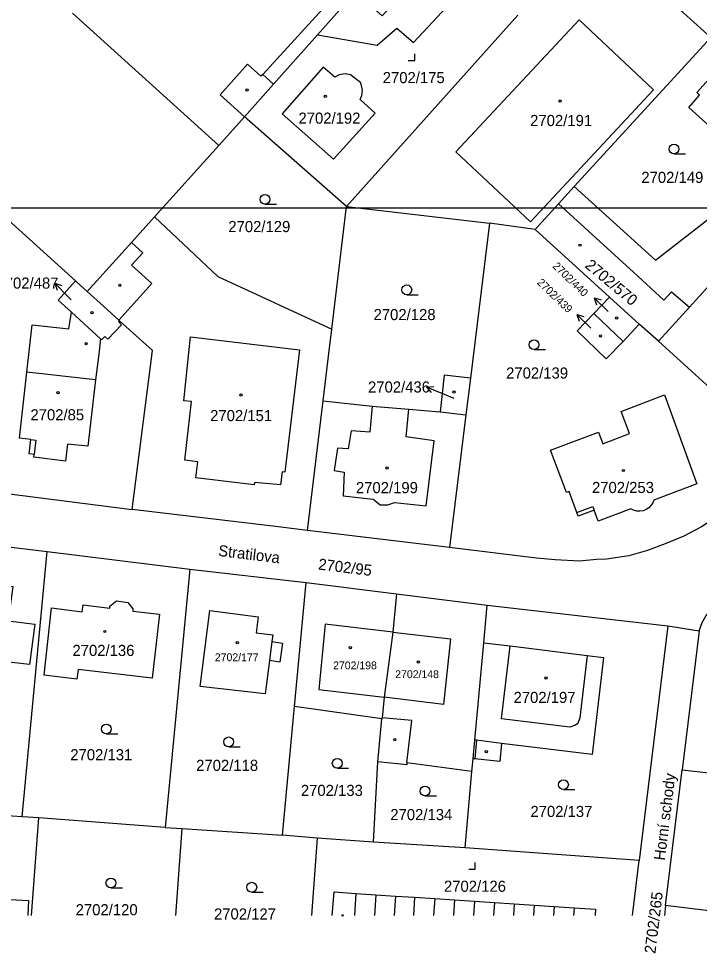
# Model space of a CAD drawing. Extents: x -496682 to -495907, y -1088575 to -1088018.
# Drawn here: x -496399.3 to -496295.2, y -1088575.2 to -1088432.3 of the extents above; entities that cross this region are included whole.
import ezdxf

# ---------------------------------------------------------------- set-up
doc = ezdxf.new("R2010")
doc.units = 0
for name, color, linetype in [('Hranice parcel', 7, 'Continuous'), ('Parcelní čísla', 7, 'Continuous'), ('Pop  PČ popisy', 7, 'Continuous'), ('Vnitřní kresba', 7, 'Continuous'), ('Vrstva 63', 7, 'Continuous'), ('Značky budov', 7, 'Continuous'), ('Značky kultur', 7, 'Continuous')]:
    doc.layers.add(name, color=color, linetype=linetype)

msp = doc.modelspace()

# ---------------------------------------------------------------- linework, layer by layer
at = {"layer": 'Hranice parcel'}
for p, q in [((-496322.98, -1088431.74), (-496349.17, -1088461.01)), ((-496368.72, -1088451.67), (-496364.78, -1088447.29)), ((-496349.17, -1088461.01), (-496364.78, -1088447.29)), ((-496378.57, -1088462.59), (-496368.72, -1088451.67)), ((-496316.74, -1088460.58), (-496314.33, -1088457.95)), ((-496320.32, -1088464.49), (-496316.74, -1088460.58)), ((-496351.43, -1088479.75), (-496349.17, -1088461.01)), ((-496349.17, -1088461.01), (-496327.31, -1088463.52)), ((-496390.64, -1088472.36), (-496401.99, -1088462.09)), ((-496327.31, -1088463.52), (-496330.22, -1088487.27)), ((-496320.32, -1088464.49), (-496327.31, -1088463.52)), ((-496308.94, -1088474.84), (-496320.32, -1088464.49)), ((-496311.35, -1088477.35), (-496308.94, -1088474.84)), ((-496304.39, -1088478.97), (-496308.94, -1088474.84)), ((-496386.81, -1088481.22), (-496391.24, -1088477.18)), ((-496306.88, -1088481.63), (-496311.35, -1088477.35)), ((-496296.73, -1088476.39), (-496301.48, -1088481.61)), ((-496304.39, -1088478.97), (-496306.88, -1088481.63)), ((-496301.48, -1088481.61), (-496304.39, -1088478.97)), ((-496301.48, -1088481.61), (-496282.64, -1088498.73)), ((-496330.22, -1088487.27), (-496330.91, -1088492.86)), ((-496355.16, -1088510.55), (-496352.76, -1088490.73)), ((-496334.86, -1088492.38), (-496330.91, -1088492.86)), ((-496330.91, -1088492.86), (-496333.4, -1088513.15)), ((-496333.4, -1088513.15), (-496355.16, -1088510.55)), ((-496413.5, -1088511.53), (-496394.97, -1088513.78)), ((-496398.8, -1088554.34), (-496394.97, -1088513.78)), ((-496394.97, -1088513.78), (-496373.13, -1088516.44)), ((-496373.13, -1088516.44), (-496376.91, -1088555.96)), ((-496373.13, -1088516.44), (-496355.34, -1088518.51)), ((-496357.11, -1088537.48), (-496355.34, -1088518.51)), ((-496355.34, -1088518.51), (-496341.52, -1088520.23)), ((-496341.52, -1088520.23), (-496327.65, -1088521.96)), ((-496328.17, -1088527.72), (-496327.65, -1088521.96)), ((-496327.65, -1088521.96), (-496300.01, -1088525.15)), ((-496300.01, -1088525.15), (-496304.43, -1088561.01)), ((-496300.01, -1088525.15), (-496295.23, -1088525.87)), ((-496295.23, -1088525.87), (-496297.81, -1088547.13)), ((-496358.95, -1088557.14), (-496357.11, -1088537.48)), ((-496343.76, -1088539.36), (-496357.11, -1088537.48)), ((-496344.37, -1088545.92), (-496343.76, -1088539.36)), ((-496345.03, -1088558.23), (-496344.37, -1088545.92)), ((-496330.02, -1088547.42), (-496329.78, -1088545.45)), ((-496331.02, -1088559.09), (-496330.02, -1088547.42)), ((-496300.36, -1088567.89), (-496297.81, -1088547.13)), ((-496297.81, -1088547.13), (-496255.13, -1088552.31)), ((-496398.8, -1088554.34), (-496417.53, -1088552.98)), ((-496396.26, -1088554.52), (-496398.8, -1088554.34)), ((-496397.38, -1088569.45), (-496396.26, -1088554.52)), ((-496376.91, -1088555.96), (-496396.26, -1088554.52)), ((-496376.91, -1088555.96), (-496374.34, -1088556.11)), ((-496375.31, -1088569.45), (-496374.34, -1088556.11)), ((-496374.34, -1088556.11), (-496358.95, -1088557.14)), ((-496353.66, -1088557.62), (-496358.95, -1088557.14)), ((-496353.66, -1088557.62), (-496354.53, -1088569.45)), ((-496345.03, -1088558.23), (-496353.66, -1088557.62)), ((-496331.02, -1088559.09), (-496345.03, -1088558.23)), ((-496304.43, -1088561.01), (-496331.02, -1088559.09)), ((-496305.44, -1088569.45), (-496304.43, -1088561.01)), ((-496347.76, -1088566.06), (-496347.98, -1088569.45)), ((-496347.76, -1088566.06), (-496344.71, -1088566.26)), ((-496344.71, -1088566.26), (-496344.92, -1088569.45)), ((-496344.71, -1088566.26), (-496341.67, -1088566.46)), ((-496341.67, -1088566.46), (-496341.87, -1088569.45)), ((-496341.67, -1088566.46), (-496338.77, -1088566.65)), ((-496338.77, -1088566.65), (-496338.95, -1088569.45)), ((-496338.77, -1088566.65), (-496335.68, -1088566.85)), ((-496335.68, -1088566.85), (-496335.85, -1088569.45)), ((-496335.68, -1088566.85), (-496332.64, -1088567.05)), ((-496332.64, -1088567.05), (-496332.8, -1088569.45)), ((-496332.64, -1088567.05), (-496329.59, -1088567.25)), ((-496329.59, -1088567.25), (-496329.73, -1088569.45)), ((-496329.59, -1088567.25), (-496326.55, -1088567.45)), ((-496326.55, -1088567.45), (-496326.68, -1088569.45)), ((-496326.55, -1088567.45), (-496323.51, -1088567.65)), ((-496323.51, -1088567.65), (-496323.63, -1088569.45)), ((-496323.51, -1088567.65), (-496320.46, -1088567.85)), ((-496320.46, -1088567.85), (-496320.57, -1088569.45)), ((-496320.46, -1088567.85), (-496317.42, -1088568.05)), ((-496317.42, -1088568.05), (-496317.51, -1088569.45)), ((-496317.42, -1088568.05), (-496314.37, -1088568.25)), ((-496314.37, -1088568.25), (-496314.45, -1088569.45)), ((-496300.36, -1088567.89), (-496300.54, -1088569.45))]:
    msp.add_line(p, q, dxfattribs=at)
for points in [[(-496353.62, -1088434.72), (-496347.79, -1088428.16), (-496343.74, -1088431.85), (-496329.03, -1088415.71), (-496329.94, -1088414.89), (-496330.57, -1088414.27), (-496328.66, -1088412.18), (-496329.87, -1088411.04), (-496330.29, -1088409.02), (-496320.05, -1088397.68)], [(-496353.62, -1088434.72), (-496344.49, -1088436.33), (-496341.48, -1088433.73), (-496338.95, -1088435.92), (-496329.51, -1088425.77)], [(-496286.81, -1088427.89), (-496293.46, -1088435.15), (-496314.33, -1088457.95)], [(-496391.09, -1088431.4), (-496372.42, -1088448.31), (-496368.72, -1088451.67)], [(-496364.78, -1088447.29), (-496360.33, -1088442.29), (-496353.62, -1088434.72)], [(-496283.32, -1088454.6), (-496289.39, -1088449.15), (-496290.42, -1088450.31), (-496292.57, -1088448.38), (-496293.21, -1088449.09), (-496296.84, -1088445.84), (-496295.16, -1088443.98), (-496295.61, -1088443.57), (-496287.2, -1088434.24), (-496282.48, -1088438.48), (-496281.67, -1088437.59), (-496278.91, -1088440.14), (-496279.72, -1088440.96), (-496274.93, -1088445.27)], [(-496350.98, -1088441.21), (-496352.73, -1088439.67), (-496359.04, -1088446.84), (-496351.17, -1088453.77), (-496344.79, -1088446.72), (-496347.09, -1088444.64), (-496346.85, -1088444.04), (-496346.74, -1088443.18), (-496346.99, -1088442.1), (-496348.56, -1088440.87), (-496349.36, -1088440.72), (-496350.32, -1088440.88), (-496350.98, -1088441.21)], [(-496268.01, -1088444.81), (-496274.79, -1088452.23), (-496288.2, -1088467.01), (-496292.3, -1088471.51), (-496296.73, -1088476.39)], [(-496314.33, -1088457.95), (-496301.91, -1088469.21), (-496284.09, -1088455.32), (-496283.32, -1088454.6)], [(-496316.74, -1088460.58), (-496305.3, -1088471.05), (-496300.65, -1088475.31), (-496299.49, -1088474.04), (-496296.73, -1088476.39)], [(-496388.84, -1088473.99), (-496382.08, -1088466.49), (-496378.57, -1088462.59)], [(-496378.57, -1088462.59), (-496368.85, -1088471.68), (-496351.43, -1088479.75)], [(-496391.24, -1088477.18), (-496393.28, -1088475.32), (-496390.64, -1088472.36)], [(-496390.64, -1088472.36), (-496390.47, -1088472.51), (-496388.84, -1088473.99)], [(-496388.84, -1088473.99), (-496386.37, -1088476.23), (-496383.99, -1088478.38), (-496383.91, -1088478.46)], [(-496386.81, -1088481.22), (-496387.08, -1088483.58), (-496387.6, -1088487.48), (-496388.73, -1088497.67), (-496391.86, -1088497.32), (-496392.17, -1088499.92), (-496397, -1088499.33), (-496396.95, -1088498.93), (-496397.74, -1088498.83), (-496397.47, -1088496.62), (-496399.19, -1088496.41), (-496398.08, -1088486.32), (-496397.28, -1088479.07), (-496391.65, -1088479.71), (-496391.24, -1088477.18)], [(-496306.88, -1088481.63), (-496309.46, -1088484.31), (-496313.92, -1088480.03), (-496311.35, -1088477.35)], [(-496383.91, -1088478.46), (-496384.05, -1088478.58), (-496383.6, -1088479.07), (-496385.69, -1088481.28), (-496386.15, -1088480.86), (-496386.65, -1088481.37), (-496386.81, -1088481.22)], [(-496381.96, -1088507.33), (-496378.87, -1088483.01), (-496383.91, -1088478.46)], [(-496352.76, -1088490.73), (-496351.88, -1088483.47), (-496351.43, -1088479.75)], [(-496330.22, -1088487.27), (-496334.22, -1088486.77), (-496334.86, -1088492.38)], [(-496305.69, -1088507.24), (-496310.68, -1088509.11), (-496311.29, -1088507.46), (-496313.75, -1088508.38), (-496313.97, -1088507.79), (-496315.1, -1088504.6), (-496315.52, -1088504.76), (-496317.97, -1088498.28), (-496310.64, -1088495.51), (-496309.98, -1088497.27), (-496305.9, -1088495.73), (-496307.18, -1088492.33), (-496300.54, -1088489.82), (-496295.6, -1088503.41), (-496302.16, -1088505.89)], [(-496352.76, -1088490.73), (-496345.27, -1088491.55), (-496339.65, -1088492), (-496334.86, -1088492.38)], [(-496282.64, -1088498.73), (-496287, -1088503.42), (-496289.92, -1088506.42), (-496292.31, -1088508.31), (-496294.86, -1088509.98), (-496297.59, -1088511.42), (-496300.41, -1088512.61), (-496303.13, -1088513.62), (-496305.98, -1088514.4), (-496309.41, -1088514.94), (-496310.93, -1088514.97), (-496313.55, -1088515.26), (-496317.24, -1088515.06), (-496320.12, -1088514.76), (-496333.4, -1088513.15)], [(-496427.43, -1088500.69), (-496425.57, -1088501.8), (-496381.96, -1088507.33)], [(-496302.16, -1088505.89), (-496302.34, -1088506.34), (-496302.61, -1088506.75), (-496302.95, -1088507.09), (-496303.36, -1088507.35), (-496303.82, -1088507.53), (-496304.3, -1088507.6), (-496304.79, -1088507.58), (-496305.26, -1088507.46), (-496305.69, -1088507.24)], [(-496355.16, -1088510.55), (-496360.04, -1088509.96), (-496381.96, -1088507.33)], [(-496295.23, -1088525.87), (-496294.76, -1088524.6), (-496294.18, -1088523.56), (-496292.73, -1088521.72), (-496280.44, -1088508.2)], [(-496401.7, -1088530.59), (-496411.17, -1088529.49), (-496410.56, -1088524.24), (-496411.46, -1088524.14), (-496410.89, -1088519.24), (-496410.59, -1088519.28), (-496410.48, -1088518.4), (-496408.38, -1088518.63), (-496408.48, -1088519.52), (-496405.68, -1088519.85), (-496405.48, -1088518.47), (-496400.24, -1088519.14), (-496400.91, -1088524.37), (-496396.87, -1088524.88), (-496397.69, -1088531.06), (-496401.7, -1088530.59)], [(-496341.52, -1088520.23), (-496342.09, -1088526.09), (-496343.43, -1088536.06), (-496343.75, -1088539.19), (-496343.76, -1088539.36)], [(-496385.39, -1088522.41), (-496385.39, -1088522.11), (-496384.36, -1088521.3), (-496382.62, -1088521.57), (-496381.87, -1088522.55), (-496381.89, -1088522.88), (-496377.78, -1088523.37), (-496378.93, -1088533.14), (-496390.24, -1088531.8), (-496390.41, -1088533.27), (-496395.43, -1088532.68), (-496394.32, -1088522.39), (-496389.59, -1088522.97), (-496389.46, -1088521.92), (-496385.39, -1088522.41)], [(-496360.97, -1088530.45), (-496361.62, -1088535.52), (-496371.55, -1088534.42), (-496370.09, -1088522.81), (-496362.68, -1088523.75), (-496362.99, -1088526.22), (-496360.46, -1088526.49), (-496360.59, -1088527.55), (-496358.97, -1088527.77), (-496359.36, -1088530.67), (-496360.97, -1088530.45)], [(-496329.78, -1088545.45), (-496329.53, -1088542.61), (-496328.17, -1088527.72)], [(-496328.17, -1088527.72), (-496324.13, -1088528.21), (-496312.38, -1088529.66)], [(-496312.38, -1088529.66), (-496309.87, -1088529.96), (-496311.62, -1088544.81), (-496325.46, -1088543.11)], [(-496325.46, -1088543.11), (-496325.75, -1088545.88), (-496329.53, -1088545.48), (-496329.78, -1088545.45)], [(-496330.02, -1088547.42), (-496339.93, -1088546.06), (-496339.96, -1088546.41), (-496344.37, -1088545.92)], [(-496351.35, -1088569.45), (-496351.07, -1088565.84), (-496347.76, -1088566.06)], [(-496404.72, -1088569.45), (-496404.57, -1088566.8), (-496397.81, -1088567.16), (-496397.94, -1088569.45)], [(-496314.37, -1088568.25), (-496311.08, -1088568.47), (-496311.14, -1088569.45)], [(-496287.95, -1088569.45), (-496300.36, -1088567.89)]]:
    msp.add_lwpolyline(points, dxfattribs=at)
at = {"layer": 'Pop  PČ popisy'}
for p, q in [((-496391.7, -1088474.87), (-496393.79, -1088472.71)), ((-496393.79, -1088472.71), (-496392.73, -1088473.08)), ((-496393.79, -1088472.71), (-496393.45, -1088473.78)), ((-496391.3, -1088475.28), (-496391.7, -1088474.87)), ((-496309.14, -1088477.04), (-496311.3, -1088474.96)), ((-496311.3, -1088474.96), (-496310.23, -1088475.29)), ((-496311.3, -1088474.96), (-496310.93, -1088476.01)), ((-496311.79, -1088479.58), (-496313.95, -1088477.5)), ((-496313.95, -1088477.5), (-496312.88, -1088477.83)), ((-496313.95, -1088477.5), (-496313.58, -1088478.55)), ((-496336.95, -1088488.62), (-496335.84, -1088488.53)), ((-496334.17, -1088489.74), (-496336.95, -1088488.62)), ((-496336.95, -1088488.62), (-496336.21, -1088489.46)), ((-496332.71, -1088490.34), (-496334.17, -1088489.74))]:
    msp.add_line(p, q, dxfattribs=at)
at = {"layer": 'Vnitřní kresba'}
for p, q in [((-496293.46, -1088435.15), (-496311.39, -1088418.91)), ((-496362, -1088440.78), (-496349.22, -1088426.85)), ((-496332.48, -1088452.62), (-496313.58, -1088432.42)), ((-496313.58, -1088432.42), (-496302.2, -1088443.15)), ((-496362, -1088440.78), (-496360.33, -1088442.29)), ((-496302.2, -1088443.15), (-496321.03, -1088463.34)), ((-496321.03, -1088463.34), (-496332.48, -1088452.62)), ((-496382.08, -1088466.49), (-496380.33, -1088468.06)), ((-496380.33, -1088468.06), (-496382.05, -1088469.97)), ((-496382.05, -1088469.97), (-496378.96, -1088472.76)), ((-496378.96, -1088472.76), (-496383.99, -1088478.38)), ((-496374.06, -1088490.72), (-496373.04, -1088480.91)), ((-496373.04, -1088480.91), (-496356.38, -1088482.92)), ((-496356.38, -1088482.92), (-496358.63, -1088501.62)), ((-496387.6, -1088487.48), (-496398.08, -1088486.32)), ((-496372.88, -1088490.84), (-496374.06, -1088490.72)), ((-496373.92, -1088499.81), (-496372.88, -1088490.84)), ((-496345.27, -1088491.55), (-496345.62, -1088495.5)), ((-496340.03, -1088496.23), (-496339.65, -1088492)), ((-496348.47, -1088495.29), (-496348.93, -1088498.04)), ((-496345.62, -1088495.5), (-496348.47, -1088495.29)), ((-496335.76, -1088496.85), (-496340.03, -1088496.23)), ((-496397.47, -1088496.62), (-496396.68, -1088496.72)), ((-496396.68, -1088496.72), (-496396.95, -1088498.93)), ((-496337, -1088506.77), (-496335.76, -1088496.85)), ((-496350.54, -1088497.97), (-496351.08, -1088501.39)), ((-496348.93, -1088498.04), (-496350.54, -1088497.97)), ((-496371.94, -1088500.04), (-496373.92, -1088499.81)), ((-496372.25, -1088502.48), (-496371.94, -1088500.04)), ((-496359.03, -1088501.57), (-496359.27, -1088503.58)), ((-496358.63, -1088501.62), (-496359.03, -1088501.57)), ((-496351.08, -1088501.39), (-496349.52, -1088501.63)), ((-496349.52, -1088501.63), (-496349.69, -1088505.23)), ((-496363.31, -1088503.59), (-496372.25, -1088502.48)), ((-496363.26, -1088503.19), (-496363.31, -1088503.59)), ((-496359.27, -1088503.58), (-496363.26, -1088503.19)), ((-496349.69, -1088505.23), (-496345.09, -1088505.75)), ((-496345.09, -1088505.75), (-496344.59, -1088506.18)), ((-496344.59, -1088506.18), (-496344.03, -1088506.6)), ((-496342.84, -1088506.62), (-496341.84, -1088506.25)), ((-496341.84, -1088506.25), (-496337, -1088506.77)), ((-496344.03, -1088506.6), (-496342.84, -1088506.62)), ((-496313.97, -1088507.79), (-496311.51, -1088506.88)), ((-496311.51, -1088506.88), (-496311.29, -1088507.46)), ((-496352.43, -1088524.87), (-496353.41, -1088534.88)), ((-496342.09, -1088526.09), (-496352.43, -1088524.87)), ((-496342.09, -1088526.09), (-496333.25, -1088527.13)), ((-496360.59, -1088527.55), (-496360.97, -1088530.45)), ((-496333.25, -1088527.13), (-496334.32, -1088537.15)), ((-496325.46, -1088539.38), (-496324.13, -1088528.21)), ((-496312.38, -1088529.66), (-496313.5, -1088539.2)), ((-496353.41, -1088534.88), (-496343.43, -1088536.06)), ((-496334.32, -1088537.15), (-496343.43, -1088536.06)), ((-496339.2, -1088539.59), (-496343.75, -1088539.19)), ((-496313.5, -1088539.2), (-496313.79, -1088540.07)), ((-496339.93, -1088546.06), (-496339.2, -1088539.59)), ((-496315.02, -1088540.61), (-496325.46, -1088539.38)), ((-496314.16, -1088540.32), (-496315.02, -1088540.61)), ((-496313.79, -1088540.07), (-496314.16, -1088540.32)), ((-496329.31, -1088542.64), (-496329.53, -1088542.61)), ((-496329.31, -1088542.64), (-496329.53, -1088545.48)), ((-496325.46, -1088543.11), (-496329.31, -1088542.64))]:
    msp.add_line(p, q, dxfattribs=at)
msp.add_lwpolyline([(-496362, -1088440.78), (-496362.27, -1088441.08), (-496364.31, -1088439.25), (-496368.51, -1088443.94), (-496364.78, -1088447.29)], dxfattribs=at)
at = {"layer": 'Vrstva 63'}
msp.add_lwpolyline([(-496137.35, -1088164.24), (-496137.35, -1088461.24), (-496557.35, -1088461.24), (-496557.35, -1088164.24)], close=True, dxfattribs=at)
at = {"layer": 'Značky budov'}
msp.add_line((-496349.93, -1088569.45), (-496349.63, -1088569.45), dxfattribs=at)
for centre in [(-496364.38, -1088443.17), (-496352.42, -1088444.14), (-496316.5, -1088444.85), (-496313.45, -1088466.91), (-496383.85, -1088473.06), (-496388.12, -1088477.24), (-496307.87, -1088478.03), (-496310.33, -1088480.78), (-496389, -1088481.97), (-496393.33, -1088489.47), (-496365.31, -1088489.84), (-496332.75, -1088489.38), (-496342.97, -1088500.98), (-496306.82, -1088501.37), (-496386.15, -1088526), (-496365.9, -1088527.72), (-496348.58, -1088528.46), (-496338.19, -1088530.68), (-496318.66, -1088533.09), (-496341.79, -1088542.52), (-496327.79, -1088544.37)]:
    msp.add_circle(centre, 0.175, dxfattribs=at)
msp.add_arc((-496349.78, -1088569.54), 0.175, 31.2705, 148.7295, dxfattribs=at)
at = {"layer": 'Značky kultur'}
for p, q in [((-496338.75, -1088438.65), (-496338.75, -1088437.65)), ((-496339.75, -1088438.65), (-496338.75, -1088438.65)), ((-496299.08, -1088452.96), (-496297.33, -1088452.96)), ((-496361.65, -1088460.66), (-496359.9, -1088460.66)), ((-496339.96, -1088474.49), (-496338.21, -1088474.49)), ((-496320.49, -1088482.89), (-496318.74, -1088482.89)), ((-496385.92, -1088541.67), (-496384.17, -1088541.67)), ((-496367.2, -1088543.63), (-496365.45, -1088543.63)), ((-496350.6, -1088546.9), (-496348.85, -1088546.9)), ((-496315.99, -1088550.17), (-496314.24, -1088550.17)), ((-496337.18, -1088551.15), (-496335.43, -1088551.15)), ((-496329.49, -1088562.33), (-496329.49, -1088561.33)), ((-496330.49, -1088562.33), (-496329.49, -1088562.33)), ((-496385.22, -1088565.21), (-496383.47, -1088565.21)), ((-496363.67, -1088565.86), (-496361.92, -1088565.86))]:
    msp.add_line(p, q, dxfattribs=at)
for centre in [(-496299.08, -1088452.21), (-496361.65, -1088459.91), (-496339.96, -1088473.74), (-496320.49, -1088482.14), (-496385.92, -1088540.92), (-496367.2, -1088542.88), (-496350.6, -1088546.15), (-496315.99, -1088549.42), (-496337.18, -1088550.4), (-496385.22, -1088564.46), (-496363.67, -1088565.11)]:
    msp.add_circle(centre, 0.75, dxfattribs=at)

# ---------------------------------------------------------------- texts
at = {"layer": 'Parcelní čísla'}
for s, height, p in [('2702/175', 1.7, (-496343.64, -1088442.13)), ('2702/192', 1.7, (-496356.53, -1088448.33)), ('2702/191', 1.7, (-496321.09, -1088448.69)), ('2702/149', 1.7, (-496304.08, -1088457.39)), ('2702/129', 1.7, (-496367.26, -1088464.91)), ('2702/487', 1.7, (-496402.72, -1088473.56)), ('2702/128', 1.7, (-496345.04, -1088478.37)), ('2702/139', 1.7, (-496324.77, -1088487.31)), ('2702/436', 1.7, (-496345.89, -1088489.45)), ('2702/85', 1.7, (-496397.53, -1088493.7)), ('2702/151', 1.7, (-496370.04, -1088493.82)), ('2702/199', 1.7, (-496347.74, -1088504.84)), ('2702/253', 1.7, (-496311.63, -1088504.82)), ('2702/136', 1.7, (-496391.1, -1088529.74)), ('2702/177', 1.2, (-496369.32, -1088530.54)), ('2702/198', 1.2, (-496351.23, -1088531.78)), ('2702/148', 1.2, (-496341.73, -1088533.13)), ('2702/197', 1.7, (-496323.63, -1088536.93)), ('2702/131', 1.7, (-496391.43, -1088545.69)), ('2702/118', 1.7, (-496372.18, -1088547.32)), ('2702/133', 1.7, (-496356.16, -1088551.15)), ('2702/134', 1.7, (-496342.48, -1088554.85)), ('2702/137', 1.7, (-496321.05, -1088554.37)), ('2702/126', 1.7, (-496334.27, -1088565.81)), ('2702/120', 1.7, (-496390.61, -1088569.4)), ('2702/127', 1.7, (-496369.45, -1088570.05))]:
    msp.add_text(s, height=height, dxfattribs=at).set_placement(p)
for s, height, rotation, p in [('2702/570', 1.7, 320, (-496312.83, -1088470.2)), ('2702/440', 1.2, 316, (-496317.74, -1088470.23)), ('2702/439', 1.2, 316, (-496320.13, -1088472.73)), ('2702/95', 1.7, 353, (-496353.57, -1088516.51)), ('2702/265', 1.7, 83, (-496301.94, -1088575.33))]:
    msp.add_text(s, height=height, rotation=rotation, dxfattribs=at).set_placement(p)
at = {"layer": 'Pop  PČ popisy'}
for s, rotation, p in [('Stratilova', 353, (-496368.88, -1088514.43)), ('Horní schody', 83, (-496300.48, -1088561.08))]:
    msp.add_text(s, height=1.7, rotation=rotation, dxfattribs=at).set_placement(p)

doc.saveas('drawing.dxf')
